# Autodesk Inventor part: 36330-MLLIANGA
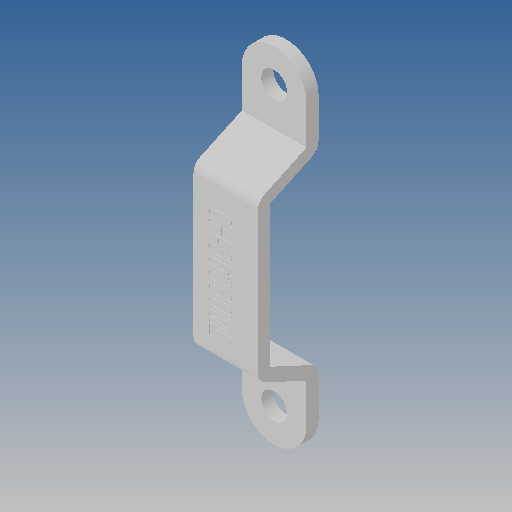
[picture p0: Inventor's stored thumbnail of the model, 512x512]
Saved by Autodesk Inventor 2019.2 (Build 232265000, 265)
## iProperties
Created: 2012-06
Part Number: 36330-MLLIANGA
Material: Ogólny
Document SubType Name: Modeling
Designer: CADENGINEERING4
Density: 1 g/cm^3
Appearance: Domyślna
Author: CADENGINEERING4
Revision Number: 2LAST_VERSION
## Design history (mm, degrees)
feature "Baza1"
node "Bryła1"
